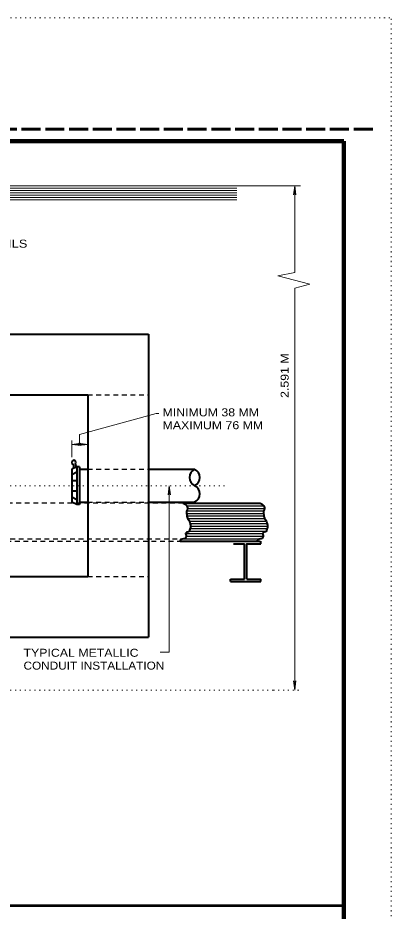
# Model space of a CAD drawing. Extents: x 312583 to 312854, y 144419 to 144597.
# Drawn here: x 312818.1 to 312853.5, y 144512 to 144596.8 of the extents above; entities that cross this region are included whole.
import ezdxf

# ---------------------------------------------------------------- set-up
doc = ezdxf.new("R2010")
doc.units = 0
doc.header["$LTSCALE"] = 0.3
for name, pattern in [('DOTTED', [1.5, 0.3, -1.2]), ('LONG_DASHED', [7.5, 6, -1.5]), ('SHORT_DASHED', [2.7, 1.5, -1.2])]:
    doc.linetypes.add(name, pattern=pattern)
doc.layers.add('1', color=7, linetype='Continuous', lineweight=13)
doc.layers.add('63', color=7, linetype='DOTTED', lineweight=13)

msp = doc.modelspace()

# ---------------------------------------------------------------- linework, layer by layer
at = {"layer": '1', "linetype": 'LONG_DASHED', "lineweight": 60}
msp.add_line((312851.75, 144586.2246), (312583.526, 144586.2246), dxfattribs=at)
at = {"layer": '1', "lineweight": 158}
for p in [(312616.5, 144585.0846), (312849, 144423.1446)]:
    msp.add_line(p, (312849, 144585.0846), dxfattribs=at)
at = {"layer": '1'}
for p, q in [((312775.6331, 144580.6299), (312838.8555, 144580.6299)), ((312844.3626, 144580.8522), (312844.2553, 144579.9859)), ((312844.3626, 144580.8522), (312844.4699, 144579.9859)), ((312844.3626, 144572.6259), (312844.3626, 144580.8522)), ((312775.6331, 144580.4076), (312838.8555, 144580.4076)), ((312775.6331, 144580.1852), (312838.8555, 144580.1852)), ((312775.6331, 144579.9552), (312838.8555, 144579.9552)), ((312844.2553, 144579.9859), (312844.3626, 144580.2619)), ((312844.4699, 144579.9859), (312844.3626, 144580.2619)), ((312775.6331, 144579.7329), (312838.8555, 144579.7329)), ((312775.6331, 144579.5106), (312838.8555, 144579.5106)), ((312844.3626, 144532.9662), (312844.3626, 144571.1232)), ((312823.2155, 144555.0769), (312823.2155, 144556.6562)), ((312823.2155, 144556.2959), (312824.0818, 144556.4032)), ((312823.2155, 144556.2959), (312824.7258, 144556.2959)), ((312823.2155, 144556.2959), (312824.0818, 144556.1886)), ((312824.0818, 144556.4032), (312823.8058, 144556.2959)), ((312824.0818, 144556.1886), (312823.8058, 144556.2959)), ((312823.8595, 144556.4032), (312824.1355, 144556.2959)), ((312824.7258, 144556.2959), (312823.8595, 144556.4032)), ((312823.8595, 144556.1886), (312824.1355, 144556.2959)), ((312824.7258, 144556.2959), (312823.8595, 144556.1886)), ((312832.4538, 144552.3706), (312832.3465, 144551.5042)), ((312832.3465, 144551.5042), (312832.4538, 144551.7802)), ((312832.4538, 144552.3706), (312832.4538, 144536.5542)), ((312832.4538, 144552.3706), (312832.5612, 144551.5042)), ((312832.5612, 144551.5042), (312832.4538, 144551.7802)), ((312831.5875, 144536.5542), (312832.4538, 144536.5542)), ((312844.2553, 144533.8326), (312844.3626, 144533.5566)), ((312844.3626, 144532.9662), (312844.2553, 144533.8326)), ((312844.4699, 144533.8326), (312844.3626, 144533.5566)), ((312844.3626, 144532.9662), (312844.4699, 144533.8326))]:
    msp.add_line(p, q, dxfattribs=at)
at = {"layer": '1', "lineweight": 40}
for p, q in [((312784.4758, 144566.7456), (312830.4758, 144566.7456)), ((312830.4758, 144566.7456), (312830.4758, 144537.9956)), ((312790.2258, 144560.9956), (312824.7258, 144560.9956)), ((312824.7258, 144560.9956), (312824.7258, 144543.7456)), ((312823.4378, 144554.0496), (312823.3612, 144554.3946)), ((312823.6448, 144554.0956), (312823.5605, 144554.4636)), ((312823.2155, 144553.9346), (312823.2155, 144550.8142)), ((312823.6908, 144553.6509), (312823.2155, 144553.4132)), ((312823.6908, 144554.1722), (312823.6908, 144550.5766)), ((312823.9362, 144554.1722), (312823.9362, 144550.5766)), ((312823.9362, 144553.9346), (312824.7258, 144553.9346)), ((312830.4758, 144553.9346), (312834.8688, 144553.9346)), ((312823.2155, 144552.8612), (312823.6908, 144552.8612)), ((312823.2155, 144551.8876), (312823.6908, 144551.8876)), ((312823.6908, 144551.0366), (312823.2155, 144551.2742)), ((312823.9362, 144550.8142), (312824.7258, 144550.8142)), ((312830.4758, 144550.8142), (312834.8688, 144550.8142)), ((312833.4888, 144547.2262), (312833.4888, 144547.1036)), ((312838.5475, 144546.8659), (312839.5892, 144546.8659)), ((312839.5892, 144543.5079), (312839.5892, 144546.8659)), ((312841.1455, 144546.8659), (312841.1455, 144547.1036)), ((312838.2705, 144543.5079), (312839.5892, 144543.5079)), ((312838.2705, 144543.2702), (312838.2705, 144543.5079)), ((312839.8268, 144543.5079), (312841.1455, 144543.5079)), ((312841.1455, 144543.2702), (312841.1455, 144543.5079)), ((312838.2705, 144543.2702), (312841.1455, 144543.2702)), ((312817.0592, 144537.9956), (312830.4758, 144537.9956))]:
    msp.add_line(p, q, dxfattribs=at)
at = {"layer": '1', "linetype": 'SHORT_DASHED', "lineweight": 25}
for p, q in [((312824.7258, 144560.9956), (312830.4758, 144560.9956)), ((312824.7258, 144553.9346), (312830.4758, 144553.9346)), ((312833.7878, 144550.6992), (312779.4465, 144550.6992)), ((312824.7258, 144550.8142), (312830.4758, 144550.8142)), ((312779.3085, 144547.3412), (312833.8722, 144547.3412)), ((312779.7455, 144547.1036), (312833.4888, 144547.1036)), ((312824.7258, 144543.7456), (312830.4758, 144543.7456))]:
    msp.add_line(p, q, dxfattribs=at)
at = {"layer": '1', "linetype": 'DOTTED'}
msp.add_line((312808.6258, 144552.3706), (312837.7285, 144552.3706), dxfattribs=at)
at = {"layer": '1', "lineweight": 35}
msp.add_line((312840.7928, 144547.2262), (312840.8388, 144547.1342), dxfattribs=at)
at = {"layer": '1', "lineweight": 53}
msp.add_line((312849, 144512.4926), (312796.3473, 144512.4926), dxfattribs=at)
at = {"layer": '1'}
for points in [[(312770.8698, 144580.8522), (312842.3325, 144580.8522), (312844.9146, 144580.8522)], [(312844.3626, 144572.6259), (312842.7603, 144572.2886), (312845.7963, 144571.4912), (312844.3626, 144571.1232)], [(312823.9515, 144556.3266), (312823.9515, 144557.2466), (312831.2042, 144559.2246), (312831.4725, 144559.2246)]]:
    msp.add_lwpolyline(points, dxfattribs=at)
at = {"layer": '1', "lineweight": 40}
for points in [[(312790.2258, 144560.9956), (312790.2258, 144543.7456), (312824.7258, 144543.7456)], [(312823.9362, 144554.1722), (312823.6908, 144554.1722), (312823.2155, 144553.9346)], [(312823.9362, 144550.5766), (312823.6908, 144550.5766), (312823.2155, 144550.8142)], [(312833.7878, 144550.6992), (312838.5475, 144550.6992), (312841.0918, 144550.6992)], [(312833.4888, 144547.1036), (312838.5475, 144547.1036), (312841.0918, 144547.1036)], [(312839.8268, 144543.5079), (312839.8268, 144546.8659), (312841.1455, 144546.8659)]]:
    msp.add_lwpolyline(points, dxfattribs=at)
at = {"layer": '1', "lineweight": 25}
for points in [[(312834.1098, 144550.4539), (312838.5475, 144550.4539), (312841.4138, 144550.4539)], [(312834.1865, 144550.2162), (312838.5475, 144550.2162), (312841.4752, 144550.2162)], [(312834.0945, 144549.7409), (312838.5475, 144549.7409), (312841.3985, 144549.7409)], [(312834.1022, 144549.9786), (312838.5475, 144549.9786), (312841.4138, 144549.9786)], [(312834.1098, 144549.4956), (312838.5475, 144549.4956), (312841.4292, 144549.4956)], [(312834.2172, 144549.2579), (312838.5475, 144549.2579), (312841.5212, 144549.2579)], [(312834.3475, 144549.0202), (312838.5475, 144549.0202), (312841.6592, 144549.0202)], [(312834.4318, 144548.7826), (312838.5475, 144548.7826), (312841.7358, 144548.7826)], [(312834.4702, 144548.5372), (312838.5475, 144548.5372), (312841.7742, 144548.5372)], [(312834.0102, 144547.8242), (312838.5475, 144547.8242), (312841.3142, 144547.8242)], [(312834.0255, 144547.5789), (312838.5475, 144547.5789), (312841.3295, 144547.5789)], [(312834.3552, 144548.0619), (312838.5475, 144548.0619), (312841.7128, 144548.0619)], [(312834.4395, 144548.2996), (312838.5475, 144548.2996), (312841.7435, 144548.2996)], [(312833.8722, 144547.3412), (312838.5475, 144547.3412), (312841.1762, 144547.3412)]]:
    msp.add_lwpolyline(points, dxfattribs=at)
at = {"layer": '1', "linetype": 'DOTTED'}
msp.add_lwpolyline([(312808.6258, 144532.9662), (312842.3325, 144532.9662), (312844.9146, 144532.9662)], dxfattribs=at)
at = {"layer": '1', "lineweight": 40}
for centre, radius, start, end in [((312823.4014, 144554.5843), 0.1983, 321.8583, 257.71168), ((312835.2404, 144553.1521), 0.8644, 115.73681, 244.26319), ((312834.4896, 144553.1521), 0.8644, 295.73681, 64.26319), ((312834.4896, 144551.5948), 0.8644, 295.73681, 64.26319)]:
    msp.add_arc(centre, radius, start, end, dxfattribs=at)
for points in [[(312833.7878, 144550.6992), (312834.0255, 144550.5689), (312834.1098, 144550.4539), (312834.1712, 144550.2699), (312834.1712, 144550.1396), (312834.1405, 144550.0629), (312834.1022, 144549.9479), (312834.0792, 144549.8176), (312834.1022, 144549.6796), (312834.1098, 144549.5799), (312834.1328, 144549.4419), (312834.1942, 144549.3039), (312834.3168, 144549.1046), (312834.4165, 144548.8592), (312834.4702, 144548.5602), (312834.4625, 144548.3379), (312834.3705, 144548.1616), (312834.3552, 144548.0389), (312834.1635, 144547.9622), (312834.0485, 144547.8932), (312834.0025, 144547.8242), (312834.0485, 144547.6402), (312833.9565, 144547.3719), (312833.7955, 144547.3182), (312833.5808, 144547.2799), (312833.4888, 144547.2262)], [(312841.0918, 144550.6992), (312841.3295, 144550.5689), (312841.4138, 144550.4539), (312841.4752, 144550.2699), (312841.4752, 144550.1396), (312841.4445, 144550.0629), (312841.4062, 144549.9479), (312841.3832, 144549.8176), (312841.4062, 144549.6796), (312841.4138, 144549.5799), (312841.4368, 144549.4419), (312841.4982, 144549.3039), (312841.6208, 144549.1046), (312841.7205, 144548.8592), (312841.7742, 144548.5602), (312841.7665, 144548.3379), (312841.6745, 144548.1616), (312841.6592, 144548.0389), (312841.4675, 144547.9622), (312841.3525, 144547.8932), (312841.3142, 144547.8242), (312841.3525, 144547.6402), (312841.2605, 144547.3719), (312841.1072, 144547.3182), (312840.8848, 144547.2799), (312840.7928, 144547.2262)]]:
    msp.add_spline(points, degree=3, dxfattribs=at)
at = {"layer": '63'}
msp.add_line((312601.2, 144596.7846), (312853.5, 144596.7846), dxfattribs=at)
msp.add_lwpolyline([(312601.2, 144418.5846), (312853.5, 144418.5846), (312853.5, 144596.7846)], dxfattribs=at)

# ---------------------------------------------------------------- texts
at = {"layer": '1'}
for s, width, p in [('SEE CURRENT 457 BY 914 MM J.B. DWG.  FOR COMPLETE DETAILS', 1.2, (312779.3545, 144574.9699)), ('MINIMUM 38 MM', 1.15, (312831.8175, 144558.9552)), ('MAXIMUM 76 MM', 1.15, (312831.8175, 144557.7352)), ('TYPICAL METALLIC', 1.15, (312818.6308, 144536.1316)), ('CONDUIT INSTALLATION', 1.1, (312818.6308, 144534.9116))]:
    msp.add_text(s, height=0.76, dxfattribs=dict(at, width=width)).set_placement(p)
at = {"layer": '1', "width": 1.15}
msp.add_text('2.591 M', height=0.76, rotation=90, dxfattribs=at).set_placement((312843.7836, 144560.7054))

doc.saveas('drawing.dxf')
